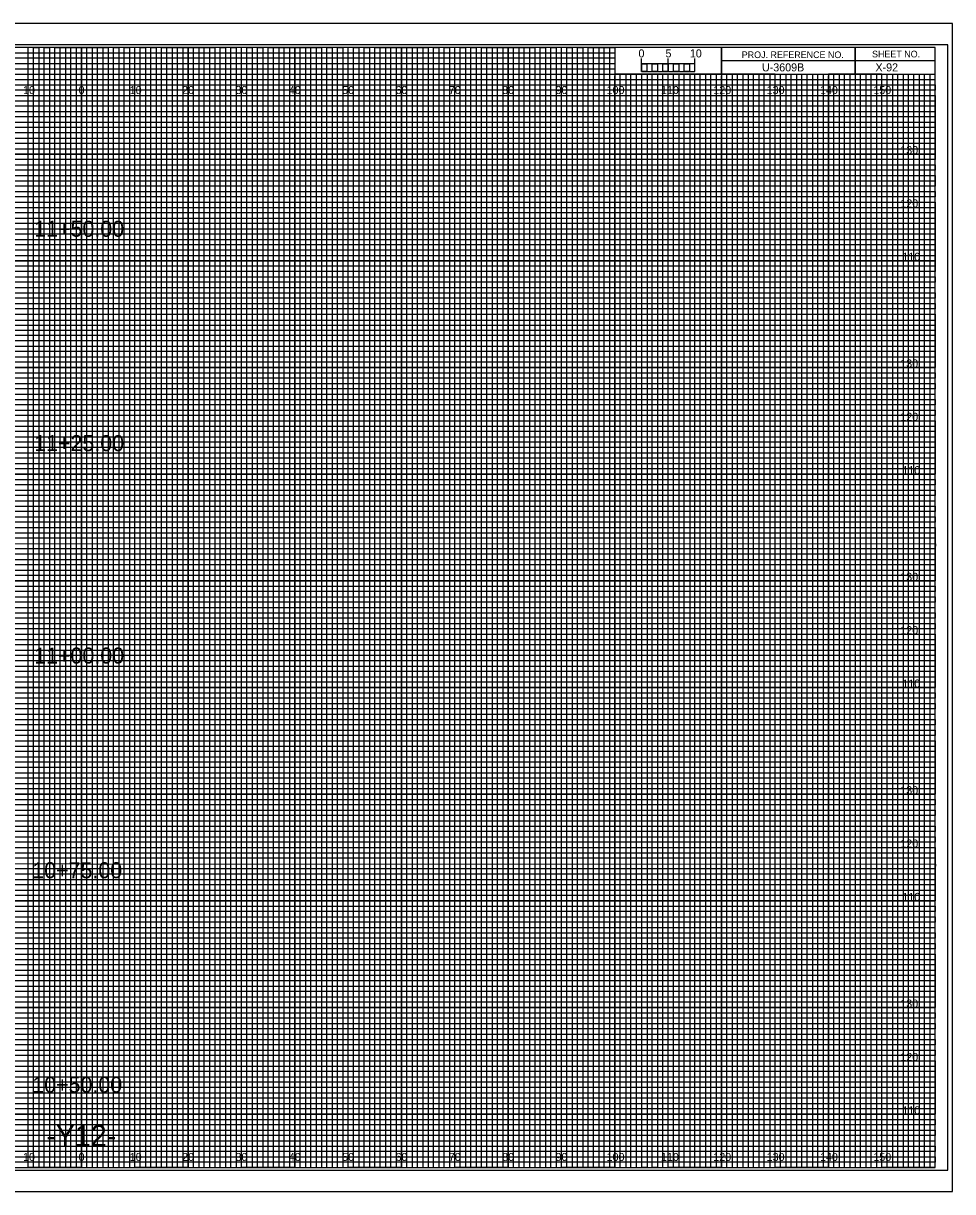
# Model space of a CAD drawing. Extents: x -13 to 323, y -5 to 874.
# Drawn here: x 149.1 to 323.3, y -4.5 to 214.5 of the extents above; entities that cross this region are included whole.
import ezdxf

# ---------------------------------------------------------------- set-up
doc = ezdxf.new("R2010")
doc.units = 0
for name, color, linetype in [('Prop XS Alignment Label', 7, 'Continuous'), ('Prop XS Bar Scale Labels', 7, 'Continuous'), ('Prop XS Elevation Labels', 7, 'Continuous'), ('Prop XS Offset Labels', 7, 'Continuous'), ('Prop XS Project Number', 7, 'Continuous'), ('Prop XS Sheet Number', 7, 'Continuous'), ('Prop XS Station Labels', 7, 'Continuous'), ('Sheet Cross Section CELL', 7, 'Continuous'), ('Sheet Cross Section Grid Major CELL', 7, 'Continuous'), ('Sheet Cross Section Grid Middle CELL', 7, 'Continuous'), ('Sheet Cross Section Grid Minor 1 CELL', 7, 'Continuous'), ('Sheet Cross Section Grid Minor 2 CELL', 7, 'Continuous'), ('Sheet Cross Section Scale CELL', 7, 'Continuous'), ('Sheet Cutting Line CELL', 7, 'Continuous'), ('Sheet DOT Grid CELL', 7, 'Continuous'), ('Sheet Plot Border Inside CELL', 7, 'Continuous'), ('Sheet Plot Border Outside CELL', 7, 'Continuous')]:
    doc.layers.add(name, color=color, linetype=linetype)

msp = doc.modelspace()

# ---------------------------------------------------------------- linework, layer by layer
at = {"layer": 'Sheet Cross Section CELL'}
for p, q in [((305, 210), (305, 205)), ((305, 205), (305, 210)), ((280, 207.5), (280, 205)), ((320, 207.49), (280, 207.49)), ((280, 205), (320, 205))]:
    msp.add_line(p, q, dxfattribs=at)
for points in [[(320, 210), (0, 210), (0, 0), (320, 0)], [(280, 210), (260, 210), (260, 205.03), (280, 205.03)], [(320, 210), (280, 210), (280, 205), (320, 205)]]:
    msp.add_lwpolyline(points, close=True, dxfattribs=at)
at = {"layer": 'Sheet Cross Section Grid Major CELL'}
for p, q in [((150, 210), (140, 210)), ((150, 0), (150, 210)), ((170, 210), (160, 210)), ((160, 210), (160, 0)), ((170, 0), (170, 210)), ((190, 210), (180, 210)), ((180, 210), (180, 0)), ((190, 0), (190, 210)), ((210, 210), (200, 210)), ((200, 210), (200, 0)), ((210, 0), (210, 210)), ((230, 210), (220, 210)), ((220, 210), (220, 0)), ((230, 0), (230, 210)), ((250, 210), (240, 210)), ((240, 210), (240, 0)), ((250, 0), (250, 210)), ((260, 210), (260, 0)), ((270, 0), (270, 205)), ((290, 205), (280, 205)), ((280, 205), (280, 0)), ((290, 0), (290, 205)), ((310, 205), (300, 205)), ((300, 205), (300, 0)), ((310, 0), (310, 205)), ((160, 0), (150, 0)), ((180, 0), (170, 0)), ((200, 0), (190, 0)), ((220, 0), (210, 0)), ((240, 0), (230, 0)), ((260, 0), (250, 0)), ((280, 0), (270, 0)), ((300, 0), (290, 0)), ((320, 0), (310, 0)), ((320, 0), (320, 0))]:
    msp.add_line(p, q, dxfattribs=at)
for points in [[(0, 200), (320, 200), (320, 190), (0, 190)], [(0, 180), (320, 180), (320, 170), (0, 170)], [(0, 160), (320, 160), (320, 150), (0, 150)], [(0, 140), (320, 140), (320, 130), (0, 130)], [(0, 120), (320, 120), (320, 110), (0, 110)], [(0, 100), (320, 100), (320, 90), (0, 90)], [(0, 80), (320, 80), (320, 70), (0, 70)], [(0, 60), (320, 60), (320, 50), (0, 50)], [(0, 40), (320, 40), (320, 30), (0, 30)], [(0, 20), (320, 20), (320, 10), (0, 10)]]:
    msp.add_lwpolyline(points, dxfattribs=at)
at = {"layer": 'Sheet Cross Section Grid Middle CELL'}
for points in [[(145, 0), (155, 0), (155, 210), (165, 210), (165, 0), (175, 0), (175, 210), (185, 210), (185, 0), (195, 0), (195, 210), (205, 210), (205, 0), (215, 0), (215, 210), (225, 210), (225, 0), (235, 0), (235, 210), (245, 210), (245, 0), (255, 0), (255, 210), (259.93, 210), (260, 210), (260, 205), (264.99, 205), (264.99, 0), (275, 0), (275, 205), (285, 205), (285, 0), (295, 0), (295, 205), (305, 205), (305, 0), (315, 0), (315, 205)], [(0, 205), (275, 205)], [(0, 185), (320, 185), (320, 195), (0, 195)], [(0, 165), (320, 165), (320, 175), (0, 175)], [(0, 145), (320, 145), (320, 155), (0, 155)], [(0, 125), (320, 125), (320, 135), (0, 135)], [(0, 105), (320, 105), (320, 115), (0, 115)], [(0, 85), (320, 85), (320, 95), (0, 95)], [(0, 65), (320, 65), (320, 75), (0, 75)], [(0, 45), (320, 45), (320, 55), (0, 55)], [(0, 25), (320, 25), (320, 35), (0, 35)], [(0, 5), (320, 5), (320, 15), (0, 15)]]:
    msp.add_lwpolyline(points, dxfattribs=at)
at = {"layer": 'Sheet Cross Section Grid Minor 1 CELL'}
for p, q in [((0, 209), (260, 209)), ((260, 209), (260, 207.98)), ((260, 207.98), (0, 207.98)), ((0, 207), (260, 207)), ((260, 205.89), (0, 205.89)), ((260, 207), (260, 205.89)), ((0, 204), (320, 204))]:
    msp.add_line(p, q, dxfattribs=at)
for points in [[(0, 203), (270, 203), (320, 203), (320, 202), (0, 202)], [(0, 201), (320, 201), (320, 199), (0, 199)], [(0, 198), (320, 198), (320, 197), (0, 196.98)], [(0, 196), (320, 196), (320, 194), (0, 194)], [(0, 193), (320, 193), (320, 192), (0, 192)], [(0, 191), (320, 191), (320, 189), (0, 189)], [(0, 188), (320, 188), (320, 187), (0, 187)], [(0, 186), (320, 186), (320, 184), (0, 184)], [(0, 183), (320, 183), (320, 182), (0, 182)], [(0, 181), (320, 181), (320, 179), (0, 179)], [(0, 178), (320, 178), (320, 177), (0, 177)], [(0, 176), (320, 176), (320, 173.95), (320, 173), (320, 172), (0, 172)], [(0, 174), (320, 174), (320, 173), (0, 173)], [(0, 171), (320, 171), (320, 169), (0, 169.03)], [(0, 169.03), (320, 169), (320, 168), (0, 168)], [(0, 167), (320, 167), (320, 166), (0, 166)], [(0, 164), (320, 164), (320, 163), (0, 163)], [(0, 162), (320, 162), (320, 161), (0, 161)], [(-0.07, 158.89), (320, 158.89), (320, 157.88), (-0.07, 157.88)], [(0, 157), (320, 157), (320, 156), (0, 156)], [(0, 154), (320, 154), (320, 153), (0, 153)], [(0, 152), (320, 152), (320, 151), (0, 151)], [(0, 149), (320, 149), (320, 148), (0, 148)], [(0, 147), (320, 147), (320, 146), (0, 146)], [(0, 144), (320, 144), (320, 143), (0, 143)], [(0, 142), (320, 142), (320, 141), (0, 141)], [(0, 139), (320, 139), (319.99, 137.98), (0, 138)], [(0, 137), (320, 137), (320, 136), (0, 136)], [(0, 134), (320, 134), (320, 133), (0, 133)], [(0, 132), (320, 132), (320, 131), (0, 131)], [(0, 129), (320, 129), (320, 128), (0, 128)], [(0, 127), (320, 127), (320, 126), (0, 126)], [(0, 124), (320, 124), (320, 123), (0, 123)], [(0, 122), (320, 122), (320, 121), (0, 121)], [(0, 119), (320, 119), (320, 118), (0, 118)], [(0, 116.99), (320.07, 116.91), (320, 116), (0, 116)], [(0, 114), (320, 114), (320, 113), (0, 113)], [(0, 112), (320, 112), (320, 111), (0, 111)], [(0, 109), (320, 109), (320, 108), (0, 108)], [(0, 107), (320, 107), (320, 106), (0, 106)], [(0, 104), (320, 104), (320, 103), (0, 103)], [(0, 102), (320, 102), (320, 101), (0, 101)], [(0, 99), (320, 99), (320, 98), (0, 98)], [(0, 97), (320, 97), (320, 96), (0, 96)], [(0, 94), (320, 94), (320, 93), (0, 93)], [(0, 92), (320, 92), (320, 91), (0, 91)], [(0, 89), (320, 89), (320, 88), (0, 88)], [(0, 87), (320, 87), (320, 86), (0, 86)], [(0, 84), (320, 84), (320, 83), (0, 83)], [(0, 82), (320, 82), (320, 81), (0, 81)], [(0, 79), (320, 79), (319.99, 77.98), (0, 78)], [(0, 77), (320, 77), (320, 76), (0, 76)], [(0, 74), (320, 74), (320, 73), (0, 73)], [(0, 72), (320, 72), (320, 71), (0, 71)], [(0, 69), (320, 69), (320, 68), (0, 68)], [(0, 67), (320, 67), (320, 66), (0, 66)], [(0, 64), (320, 64), (320, 63), (0, 63)], [(0, 62), (320, 62), (320, 61), (0, 61)], [(0, 59), (320, 59), (320, 58), (0, 58)], [(0, 56.99), (320.07, 56.91), (320, 56), (0, 56)], [(0, 54), (320, 54), (320, 53), (0, 53)], [(0, 52), (320, 52), (320, 51), (0, 51)], [(0, 49), (320, 49), (320, 48), (0, 48)], [(0, 47), (320, 47), (320, 46), (0, 46)], [(0, 44), (320, 44), (320, 43), (0, 43)], [(0, 42), (320, 42), (320, 41), (0, 41)], [(0, 39), (320, 39), (320, 38), (0, 38)], [(0, 37), (320, 37), (320, 36), (0, 36)], [(0, 34), (320, 34), (320, 33), (0, 33)], [(0, 32), (320, 32), (320, 31), (0, 31)], [(0, 29), (320, 29), (320, 28), (0, 28)], [(0, 27), (320, 27), (320, 26), (0, 26)], [(0, 24), (320, 24), (320, 23), (0, 23)], [(0, 22), (320, 22), (320, 21), (0, 21)], [(0, 19), (320, 19), (320, 18), (0, 18)], [(0, 17), (320, 17), (320, 16), (0, 16)], [(0, 14), (320, 14), (320, 13), (0, 13)], [(0, 12), (320, 12), (320, 11), (0, 11)], [(0, 9), (320, 9), (320, 8), (0, 8)], [(0, 7), (320, 7), (320, 6), (0, 6)], [(0, 4), (320, 4), (320, 3), (0, 3)], [(0, 2), (320, 2), (320, 1), (0, 1)]]:
    msp.add_lwpolyline(points, dxfattribs=at)
at = {"layer": 'Sheet Cross Section Grid Minor 2 CELL'}
for p, q in [((267, 205), (266.01, 205)), ((266.01, 205), (266.01, 0)), ((267, 0), (267, 205)), ((269, 205), (268, 205)), ((268, 205), (268, 0)), ((269, 0), (269, 205)), ((266.01, 0), (265, 0)), ((268, 0), (267, 0))]:
    msp.add_line(p, q, dxfattribs=at)
for points in [[(150, 0), (151, 0), (151, 210), (152, 210), (152, 0)], [(152, 0), (153, 0), (153, 210), (154, 210), (154, 0)], [(155, 0), (156, 0), (156, 210), (157, 210), (157, 0)], [(157, 0), (158, 0), (158, 210), (159, 210), (159, 0)], [(160, 0), (161, 0), (161, 210), (162, 210), (162, 0)], [(162, 0), (163, 0), (163, 210), (164, 210), (164, 0)], [(165, 0), (166, 0), (166, 210), (167, 210), (167, 0)], [(167, 0), (168, 0), (168, 210), (169, 210), (169, 0)], [(170, 0), (171, 0), (171, 210), (172, 210), (172, 0)], [(172, 0), (173, 0), (173, 210), (174, 210), (174, 0)], [(175, 0), (176, 0), (176, 210), (177, 210), (177, 0)], [(177, 0), (178, 0), (178, 210), (179, 210), (179, 0)], [(180, 0), (181, 0), (181, 210), (182, 210), (182, 0)], [(182, 0), (183, 0), (183, 210), (184, 210), (184, 0)], [(185, 0), (186, 0), (186, 210), (187, 210), (187, 0)], [(187, 0), (188, 0), (188, 210), (189, 210), (189, 0)], [(190, 0), (191, 0), (191, 210), (192, 210), (192, 0)], [(192, 0), (193, 0), (193, 210), (194, 210), (194, 0)], [(195, 0), (196, 0), (196, 210), (197, 210), (197, 0)], [(197, 0), (198, 0), (198, 210), (199, 210), (199, 0)], [(200, 0), (201, 0), (201, 210), (202, 210), (202, 0)], [(202, 0), (203, 0), (203, 210), (204, 210), (204, 0)], [(205, 0), (206, 0), (206, 210), (207, 210), (207, 0)], [(207, 0), (208, 0), (208, 210), (209, 210), (209, 0)], [(210, 0), (211, 0), (211, 210), (212, 210), (212, 0)], [(212, 0), (213, 0), (213, 210), (214, 210), (214, 0)], [(215, 0), (216, 0), (216, 210), (217, 210), (217, 0)], [(217, 0), (218, 0), (218, 210), (219, 210), (219, 0)], [(220, 0), (221, 0), (221, 210), (222, 210), (222, 0)], [(222, 0), (223, 0), (223, 210), (224, 210), (224, 0)], [(225, 0), (226, 0), (226, 210), (227, 210), (227, 0)], [(227, 0), (228, 0), (228, 210), (229, 210), (229, 0)], [(230, 0), (231, 0), (231, 210), (232, 210), (232, 0)], [(232, 0), (233, 0), (233, 210), (234, 210), (234, 0)], [(235, 0), (236, 0), (236, 210), (237, 210), (237, 0)], [(237, 0), (238, 0), (238, 210), (239, 210), (239, 0)], [(240, 0), (241, 0), (241, 210), (242, 210), (242, 0)], [(242, 0), (243, 0), (243, 210), (244, 210), (244, 0)], [(245, 0), (246, 0), (246, 210), (247, 210), (247, 0)], [(247, 0), (248, 0), (248, 210), (249, 210), (249, 0)], [(250, 0), (251, 0), (251, 210), (252, 210), (252, 0)], [(252, 0), (253, 0), (253, 210), (254, 210), (254, 0)], [(255, 0), (256, 0), (256, 210), (257, 210), (257, 0)], [(257, 0), (258, 0), (258, 210), (259, 210), (259, 0)], [(260, 0), (261, 0), (261, 205), (262.02, 205), (262.02, 0)], [(262, 0), (263, 0), (263, 205), (263.99, 205), (263.99, 0)], [(270, 0), (270.98, 0), (270.98, 205), (272, 205), (272, 0)], [(272, 0), (273, 0), (273, 205), (274.05, 205), (274.05, 0)], [(275, 0), (276, 0), (276, 205), (277, 205), (277, 0)], [(277, 0), (278, 0), (278, 205), (279, 205), (279, 0)], [(280, 0), (281, 0), (281, 205), (282, 205), (282, 0)], [(282, 0), (283, 0), (283, 205), (284, 205), (284, 0)], [(285, 0), (286, 0), (286, 205), (287, 205), (287, 0)], [(287, 0), (288, 0), (288, 205), (289, 205), (289, 0)], [(290, 0), (291, 0), (291, 205), (292, 205), (292, 0)], [(292, 0), (293, 0), (293, 205), (294, 205), (294, 0)], [(295, 0), (296, 0), (296, 205), (297, 205), (297, 0)], [(297, 0), (298, 0), (298, 205), (299, 205), (299, 0)], [(300, 0), (301, 0), (301, 205), (302, 205), (302, 0)], [(302, 0), (303, 0), (303, 205), (304, 205), (304, 0)], [(305, 0), (306, 0), (306, 205), (307, 205), (307, 0)], [(307, 0), (308, 0), (308, 205), (309, 205), (309, 0)], [(310, 0), (311, 0), (311, 205), (312, 205), (312, 0)], [(312, 0), (313, 0), (313, 205), (314, 205), (314, 0)], [(315, 0), (316, 0), (316, 205), (317, 205), (317, 0)], [(317, 0), (318, 0), (318, 205), (319, 205), (319, 0)]]:
    msp.add_lwpolyline(points, dxfattribs=at)
at = {"layer": 'Sheet Cross Section Scale CELL'}
for p, q in [((265, 205.49), (265, 207.9)), ((265, 206.9), (265, 207.9)), ((270, 205.49), (270, 207.9)), ((275, 205.49), (275, 207.9)), ((275, 206.9), (275, 207.9))]:
    msp.add_line(p, q, dxfattribs=at)
for points in [[(275, 206.9), (265, 206.9), (265, 205.49), (275, 205.49)], [(265, 206.9), (266, 206.9), (266, 205.49), (265, 205.49)], [(267, 206.9), (268, 206.9), (268, 205.49), (267, 205.49)], [(269, 206.9), (270, 206.9), (270, 205.49), (269, 205.49)], [(271, 206.9), (272, 206.9), (272, 205.49), (271, 205.49)], [(273, 206.9), (274, 206.9), (274, 205.49), (273, 205.49)]]:
    msp.add_lwpolyline(points, close=True, dxfattribs=at)
at = {"layer": 'Sheet Cutting Line CELL'}
for p, q in [((323.3, 214.5), (-13.4, 214.5)), ((-13.4, -4.5), (323.3, -4.5))]:
    msp.add_line(p, q, dxfattribs=at)
at = {"layer": 'Sheet DOT Grid CELL'}
for p, q in [((150, 0), (150, 210)), ((160, 0), (160, 210)), ((170, 0), (170, 210)), ((180, 0), (180, 210)), ((190, 0), (190, 210)), ((200, 0), (200, 210)), ((210, 0), (210, 210)), ((220, 0), (220, 210)), ((230, 0), (230, 210)), ((240, 0), (240, 210)), ((250, 0), (250, 210)), ((260, 0), (260, 204.69)), ((270, 0), (270, 204.69)), ((280, 0), (280, 204.69)), ((290, 0), (290, 204.69)), ((300, 0), (300, 204.69)), ((310, 0), (310, 204.69)), ((0, 200), (320, 200)), ((0, 190), (320, 190)), ((0, 180), (320, 180)), ((0, 170), (320, 170)), ((0, 160), (320, 160)), ((0, 150), (320, 150)), ((0, 140), (320, 140)), ((0, 130), (320, 130)), ((0, 120), (320, 120)), ((0, 110), (320, 110)), ((0, 100), (320, 100)), ((0, 90), (320, 90)), ((0, 80), (320, 80)), ((0, 70), (320, 70)), ((0, 60), (320, 60)), ((0, 50), (320, 50)), ((0, 40), (320, 40)), ((0, 30), (320, 30)), ((0, 20), (320, 20)), ((0, 10), (320, 10))]:
    msp.add_line(p, q, dxfattribs=at)
at = {"layer": 'Sheet Plot Border Inside CELL'}
msp.add_lwpolyline([(-10.8, -0.5), (322.4, -0.5), (322.4, 210.5), (-10.8, 210.5)], close=True, dxfattribs=at)
at = {"layer": 'Sheet Plot Border Outside CELL'}
msp.add_lwpolyline([(-13.4, -4.5), (323.3, -4.5), (323.3, 214.5), (-13.4, 214.5)], close=True, dxfattribs=at)

# ---------------------------------------------------------------- texts
at = {"layer": 'Prop XS Alignment Label'}
msp.add_text('-Y12-', height=4, dxfattribs=at).set_placement((153.41, 4))
at = {"layer": 'Prop XS Bar Scale Labels'}
for s, p in [('5', (269.47, 208.12)), ('10', (274.04, 208.12))]:
    msp.add_text(s, height=1.5, dxfattribs=at).set_placement(p)
at = {"layer": 'Prop XS Elevation Labels'}
for s, p in [('130', (313.49, 190)), ('120', (313.5, 180)), ('110', (313.88, 170)), ('130', (313.49, 150)), ('120', (313.5, 140)), ('110', (313.88, 130)), ('130', (313.49, 110)), ('120', (313.5, 100)), ('110', (313.88, 90)), ('130', (313.49, 70)), ('120', (313.5, 60)), ('110', (313.88, 50)), ('130', (313.49, 30)), ('120', (313.5, 20)), ('110', (313.88, 10))]:
    msp.add_text(s, height=1.5, dxfattribs=at).set_placement(p)
at = {"layer": 'Prop XS Offset Labels'}
for s, p in [('10', (149.04, 201.25)), ('0', (159.45, 201.25)), ('0', (159.45, 201.25)), ('10', (169.04, 201.25)), ('20', (178.86, 201.25)), ('30', (188.86, 201.25)), ('40', (198.86, 201.25)), ('50', (208.86, 201.25)), ('60', (218.86, 201.25)), ('70', (228.86, 201.25)), ('80', (238.86, 201.25)), ('90', (248.86, 201.25)), ('100', (258.44, 201.25)), ('110', (268.62, 201.25)), ('120', (278.44, 201.25)), ('130', (288.44, 201.25)), ('140', (298.44, 201.25)), ('150', (308.44, 201.25)), ('10', (149.04, 1.25)), ('0', (159.45, 1.25)), ('0', (159.45, 1.25)), ('10', (169.04, 1.25)), ('20', (178.86, 1.25)), ('30', (188.86, 1.25)), ('40', (198.86, 1.25)), ('50', (208.86, 1.25)), ('60', (218.86, 1.25)), ('70', (228.86, 1.25)), ('80', (238.86, 1.25)), ('90', (248.86, 1.25)), ('100', (258.44, 1.25)), ('110', (268.62, 1.25)), ('120', (278.44, 1.25)), ('130', (288.44, 1.25)), ('140', (298.44, 1.25)), ('150', (308.44, 1.25))]:
    msp.add_text(s, height=1.5, dxfattribs=at).set_placement(p)
at = {"layer": 'Prop XS Project Number'}
msp.add_text('U-3609B', height=1.5, dxfattribs=at).set_placement((287.56, 205.5))
at = {"layer": 'Prop XS Sheet Number'}
msp.add_text('X-92', height=1.5, dxfattribs=at).set_placement((308.83, 205.5))
at = {"layer": 'Prop XS Station Labels'}
for s, p in [('11+50.00', (151.13, 174.5)), ('11+25.00', (151.13, 134.31)), ('11+00.00', (151.13, 94.49)), ('10+75.00', (150.77, 54.25)), ('10+50.00', (150.77, 14.05))]:
    msp.add_text(s, height=3, dxfattribs=at).set_placement(p)
at = {"layer": 'Sheet Cross Section CELL'}
for s, p in [('PROJ. REFERENCE NO.', (283.77, 207.99)), ('SHEET NO.', (308.19, 208.12))]:
    msp.add_text(s, height=1.25, dxfattribs=at).set_placement(p)
at = {"layer": 'Sheet Cross Section Scale CELL'}
msp.add_text('0', height=1.5, dxfattribs=at).set_placement((264.41, 208.12))

doc.saveas('drawing.dxf')
